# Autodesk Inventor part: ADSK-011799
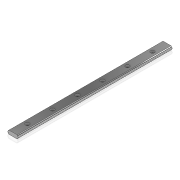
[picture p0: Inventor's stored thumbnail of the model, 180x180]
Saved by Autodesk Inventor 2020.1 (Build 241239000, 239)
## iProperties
Created: 1999-12
Part Number: ADSK-011799
Material: Acier (alliage faible hypertrempé)
Document SubType Name: Modeling
Designer: sspink
Density: 7.84 g/cm^3
Appearance: Chrom - poliert
Mass: 4952.53 g
Surface Area: 1030.62 cm^2
Volume: 631.701 cm^3
Control State: 0
Master: False
Checked Out: False
Shininess: 0.0
Length Units: 11269
Angle Units: 11279
Time Units: 11290
Mass Units: 11283
Length Display Precision: 3
Angle Display Precision: 2
Compacted: True
Dimensions: 52x18x770 mm
Mass: 4,953 kg
DocNumber: ADSK-011799.ipt
Folder: 01 - Themengebiete\Simplification\01 - Packaging machine\
VDS_Category: 3D Komponenten
Density: 0.0
Volumn: 0.0
Area: 0.0
PropertySet Name: Model Information
Author: sspink
Revision Number: -
Title: linear guide
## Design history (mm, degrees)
node "Extrusion1" dims "d22" = 770, "d23" = 0
node "Hole1" dims "d28" = 11, "d29" = 19, "d30" = 11.5, "d31" = 60 deg, "d32" = 8, "d33" = 118 deg, "d44" = 6
node "Solide1"
node "Corps solides"
node "Corps surfaciques"
sketch "Sketch1"
  geometry: L1 (0, 9)-(0, -25); L2 (-21, -5)-(-21, 5); L3 (-23, 6.083)-(-20.083, 9); L4 (-20.083, 9)-(0, 9); L5 (0, 9)-(20.083, 9); L6 (20.083, 9)-(23, 6.083); L7 (21, 5)-(21, -5); L8 (21, -5)-(20.778, -5); L9 (-23, -6.083)-(-23, -4.583); L10 (-23, 6.083)-(-23, 4.583); L11 (23, 4.583)-(23, 6.083); L12 (23, -4.583)-(23, -6.083); L13 (-23, -6.083)-(-20.083, -9); L14 (-20.083, -9)-(20.083, -9); L15 (20.083, -9)-(23, -6.083); L16 (-21, 0)-(21, 0); A1 r 5 centre (-21, 0) between (-23, -4.583) and (-23, 4.583); A2 r 5 centre (21, 0) between (23, 4.583) and (23, -4.583); 1 further point
  constraints: 32 end point, 6 equal length, 4 parallel, 4 point on circle, 3 collinear, 3 midpoint, 3 perpendicular, 2 centre point, 1 equal radius, 1 point on line, 1 vertical
  dimensions: "d0" = 34 distance of L1.start L1.end; "d1" = 42 distance between parallel lines of L7 L2; "d2" = 10 diameter of A1; "d4" = 10 distance of L2.start L2.end; "d7" = 23 distance between parallel lines of L11 L1; "d8" = 23 distance between parallel lines of L1 L9; "d9" = 23 distance between parallel lines of L10 L1; "d10" = 23 distance between parallel lines of L12 L1; "d11" = 1.5 distance of L3.start L10.end; "d12" = 1.5 distance of L9.start L9.end (= d11); "d34" = 18 distance between parallel lines of L14 L4; "d35" = 9 distance between parallel lines of L14 L16 (= 0.5 x d34); "d36" = 42 distance of L16.end L16.start
sketch "Sketch2"
  geometry: L1 (0, -770)-(40.165, -770) reference; L2 (40.165, 0)-(0, 0) reference; L3 (20.083, -770)-(20.083, 0); 6 further points
  constraints: 6 point on line, 2 end point, 2 midpoint
  dimensions: "d38" = 72.5 distance from line of point (20.083, -72.5) L2; "d39" = 125 distance of point (20.083, -197.5) point (20.083, -72.5); "d40" = 125 distance of point (20.083, -322.5) point (20.083, -197.5); "d41" = 125 distance of point (20.083, -447.5) point (20.083, -322.5); "d42" = 125 distance of point (20.083, -572.5) point (20.083, -447.5); "d43" = 125 distance of point (20.083, -697.5) point (20.083, -572.5)
